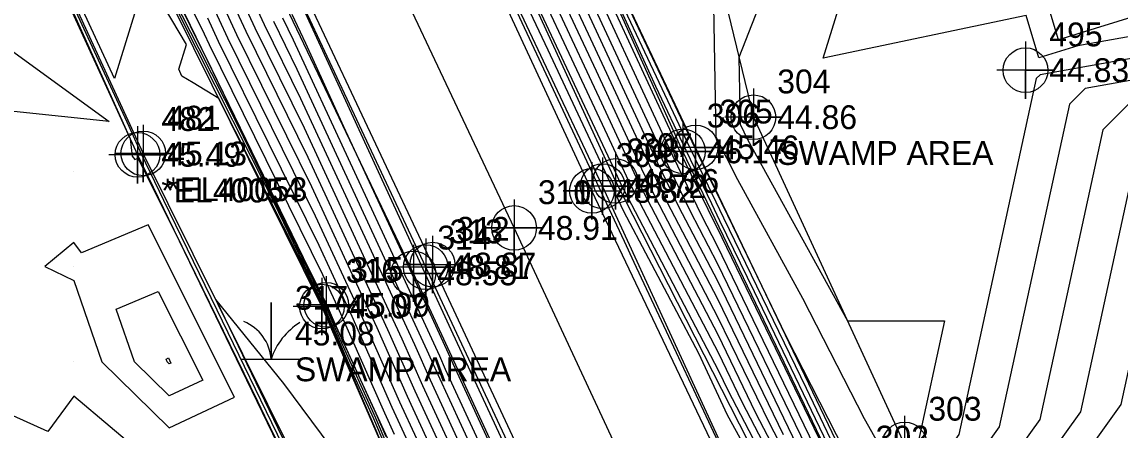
# Model space of a CAD drawing. Extents: x 2090860 to 2091277, y 159470 to 160080.
# Drawn here: x 2090954.6 to 2091069.7, y 159862.9 to 159905.6 of the extents above; entities that cross this region are included whole.
import ezdxf

# ---------------------------------------------------------------- set-up
doc = ezdxf.new("R2010")
doc.units = 0
for name, color, linetype in [('DTM Contours Major', 7, 'Continuous'), ('DTM Contours Minor', 7, 'Continuous'), ('Exist DTM Breakline', 7, 'Continuous'), ('Exist DTM Breakline Cogo Comment', 7, 'Continuous'), ('Exist DTM Breakline Cogo Elevation', 7, 'Continuous'), ('Exist DTM Breakline Cogo Number', 7, 'Continuous'), ('Exist DTM Breakline Cogo Point CELL', 7, 'Continuous'), ('Exist DTM Breakline Underwater', 7, 'Continuous'), ('Exist DTM Crownline', 7, 'Continuous'), ('Exist DTM Crownline Cogo Elevation', 7, 'Continuous'), ('Exist DTM Crownline Cogo Number', 7, 'Continuous'), ('Exist DTM Crownline Cogo Point CELL', 7, 'Continuous'), ('Exist DTM QL2 LIDAR Elevation Point', 7, 'Continuous'), ('Exist DTM Regular Point CELL', 7, 'Continuous'), ('Exist DTM Regular Point Cogo Elevation', 7, 'Continuous'), ('Exist DTM Regular Point Cogo Number', 7, 'Continuous'), ('Exist Hydro Swamp or Marsh', 7, 'Continuous'), ('Exist Hydro Swamp or Marsh Cogo Comment', 7, 'Continuous'), ('Exist Hydro Swamp or Marsh Cogo Elevation', 7, 'Continuous'), ('Exist Hydro Swamp or Marsh Cogo Number', 7, 'Continuous'), ('Exist Roads EOP', 7, 'Continuous'), ('Exist Roads EOP Cogo Elevation', 7, 'Continuous'), ('Exist Roads EOP Cogo Number', 7, 'Continuous'), ('Exist Roads EOP Cogo Point CELL', 7, 'Continuous'), ('Exist Roads EOT', 7, 'Continuous'), ('Exist Roads EOT Cogo Elevation', 7, 'Continuous'), ('Exist Roads EOT Cogo Number', 7, 'Continuous'), ('Exist Roads EOT Cogo Point CELL', 7, 'Continuous')]:
    doc.layers.add(name, color=color, linetype=linetype)

msp = doc.modelspace()

# ---------------------------------------------------------------- linework, layer by layer
at = {"layer": 'DTM Contours Major'}
for points in [[(2091039.97, 159928.18), (2091029.72, 159901.93), (2091029.84, 159894.93), (2091030.64, 159893.33), (2091041.09, 159874.33), (2091046.74, 159874.32), (2091051.28, 159874.32), (2091048.51, 159861.61), (2091048.02, 159860.92), (2091052.61, 159846.51), (2091052.56, 159846.24), (2091064.7, 159822.8), (2091063.82, 159819.49), (2091056.74, 159812.83), (2091055.87, 159811.45), (2091055.8, 159811.41), (2091054.88, 159810.97), (2091050.57, 159808.88), (2091033.91, 159797.01), (2091031.48, 159794.62), (2091026.53, 159778.36)], [(2091083.65, 159906.42), (2091065.23, 159903.13), (2091061.17, 159901.88), (2091059.83, 159906.32), (2091038.54, 159901.84), (2091046.68, 159928.13)], [(2090955.45, 159918.84), (2090963.16, 159912.58), (2090966.53, 159906.94), (2090964.27, 159899.73), (2090955.45, 159918.84)], [(2091040.77, 159857.8), (2091031.34, 159877.37), (2091027.73, 159884.81), (2091026.88, 159886.57), (2091024.18, 159892.18), (2091021.02, 159898.88), (2091011.64, 159919.46)], [(2091041.05, 159844.71), (2091030.07, 159865.8), (2091027.57, 159870.96), (2091018.54, 159888.26), (2091017.95, 159889.49), (2091015.95, 159893.79), (2091005.23, 159916.67)], [(2090967.46, 159914.98), (2090973.01, 159903.6), (2090973.34, 159902.96), (2090973.84, 159901.97), (2090984.06, 159880.95), (2090986.46, 159876.09), (2090986.5, 159876), (2090986.52, 159875.97), (2090987.34, 159874.09), (2090991.85, 159864.2), (2090992.7, 159862.2)], [(2090974.73, 159909.42), (2090977.08, 159904.33), (2090984.93, 159888.39), (2090990.07, 159877.29), (2090991.77, 159873.61), (2090994.95, 159866.4), (2090999.75, 159856)], [(2091035.84, 159861.21), (2091027.5, 159878.46), (2091023.43, 159886.26), (2091021.18, 159890.91), (2091013.64, 159907.17)], [(2090980.93, 159905.73), (2090983.4, 159900.7), (2090993.64, 159878.58), (2090997.02, 159871.25), (2090998.15, 159868.69), (2091007.95, 159847.44)], [(2091091.58, 159898.64), (2091075.46, 159895.75), (2091071.36, 159891.65), (2091065.51, 159864.77), (2091059.16, 159855.9), (2091062.53, 159845.34), (2091062.38, 159844.53), (2091071.24, 159827.42), (2091068.47, 159817.05), (2091062.55, 159811.48), (2091060.26, 159801.48), (2091046.88, 159791.94), (2091037.59, 159782.8), (2091031.99, 159764.38), (2091026.69, 159760.21), (2091021.29, 159752.69), (2091014.87, 159747.47), (2091001.67, 159730.12), (2090998.42, 159727.26), (2090990.82, 159719.67), (2090976.25, 159706.99)], [(2090968.87, 159877.39), (2090973.52, 159868.09), (2090970, 159866.45), (2090966.37, 159870), (2090964.45, 159875.55), (2090968.87, 159877.39)], [(2091016.71, 159800.2), (2091008.38, 159811.91), (2091004.99, 159818.47), (2091002.26, 159829.04), (2091000.51, 159832.57), (2090997.86, 159833.56), (2090989.84, 159850.89), (2090987.9, 159859.84), (2090982.04, 159867.75), (2090974.9, 159876.54), (2090983.75, 159858.2), (2090986.81, 159851.93), (2090996.12, 159832.68), (2090997.83, 159829.17), (2090999.89, 159824.93), (2091004.42, 159815.54), (2091007.3, 159809.55), (2091015.2, 159792.84), (2091016.71, 159800.2)]]:
    msp.add_lwpolyline(points, dxfattribs=at)
at = {"layer": 'DTM Contours Minor'}
for points in [[(2090953.06, 159921.96), (2090965.05, 159895.34), (2090965.36, 159894.66), (2090965.92, 159893.4), (2090966.12, 159891.57), (2090966.4, 159891.21), (2090966.74, 159891.35), (2090970.6, 159883.65), (2090979.25, 159865.89), (2090980, 159864.34), (2090992.07, 159839.55), (2090993.27, 159837.07), (2090997.16, 159829.09), (2091001.85, 159819.43), (2091003.89, 159815.2), (2091014.81, 159792.51), (2091016.87, 159788.26), (2091017.43, 159786.84), (2091024.63, 159765.9)], [(2091041.7, 159858.95), (2091034.7, 159872.63), (2091028.55, 159885.34), (2091025.32, 159892.03), (2091025.1, 159892.47), (2091012.73, 159918.74)], [(2091040.87, 159848.3), (2091032.95, 159863.5), (2091027.53, 159874.71), (2091020.98, 159887.26), (2091019.56, 159890.2), (2091014.79, 159900.48), (2091006.87, 159917.39)], [(2091034.39, 159862.36), (2091027.52, 159876.59), (2091022.21, 159886.76), (2091020.37, 159890.55), (2091014.22, 159903.83), (2091007.7, 159917.75)], [(2091040.16, 159857.78), (2091027.45, 159884.09), (2091027.09, 159884.77), (2091023.61, 159891.97), (2091011.91, 159917.21)], [(2091041.13, 159842.92), (2091028.63, 159866.94), (2091027.59, 159869.09), (2091017.32, 159888.76), (2091017.14, 159889.13), (2091016.53, 159890.45), (2091004.41, 159916.31)], [(2091040.96, 159846.5), (2091031.51, 159864.65), (2091027.55, 159872.84), (2091019.76, 159887.76), (2091018.75, 159889.84), (2091015.37, 159897.14), (2091006.05, 159917.03)], [(2090968.28, 159915.35), (2090973.67, 159904.41), (2090974.2, 159903.27), (2090986.08, 159879.16), (2090987.4, 159876.32), (2090987.83, 159875.38), (2090992.56, 159864.68), (2090993.6, 159862.42)], [(2091039.08, 159845.24), (2091028.52, 159864.43), (2091025.51, 159870.89), (2091017.65, 159885.76), (2091016.26, 159888.76), (2091009.72, 159902.68), (2091003.49, 159915.92)], [(2091018.49, 159801.2), (2091016.34, 159804.22), (2091005.91, 159824.4), (2091004.75, 159828.91), (2091001.89, 159834.69), (2091000.66, 159835.15), (2090996.96, 159843.16), (2090993.72, 159858.07), (2090991.18, 159864.04), (2090990.78, 159864.92), (2090986.1, 159875.84), (2090983.69, 159880.8), (2090975.23, 159897.62), (2090972.54, 159899.28), (2090971.35, 159899.98), (2090971.03, 159900.71), (2090971.84, 159903.3), (2090965.56, 159913.82)], [(2090975.78, 159914.43), (2090979.97, 159905.38), (2090983.78, 159897.63), (2090992.75, 159878.26), (2090995.71, 159871.84), (2090997.35, 159868.12), (2091005.9, 159849.58)], [(2091038.72, 159858.92), (2091027.46, 159882.21), (2091025.87, 159885.26), (2091022.8, 159891.62), (2091012.48, 159913.86)], [(2091073.27, 159906.87), (2091063.23, 159903.77), (2091059.94, 159914.75)], [(2090957.42, 159912.81), (2090965.77, 159894.72), (2090966.22, 159893.71), (2090967.09, 159891.81), (2090969.43, 159886.95), (2090975.02, 159875.46), (2090981.88, 159861.27), (2090989.44, 159845.74), (2090994.7, 159834.88), (2090997.49, 159829.13), (2091000.87, 159822.18), (2091004.15, 159815.37), (2091013, 159797), (2091016.23, 159790.16), (2091018.49, 159801.2)], [(2090975.43, 159912.76), (2090979, 159905.03), (2090984.17, 159894.55), (2090991.86, 159877.93), (2090994.39, 159872.43), (2090996.55, 159867.54), (2091003.85, 159851.72)], [(2091026.97, 159913.29), (2091027.29, 159893.6), (2091029.56, 159889.12), (2091036.39, 159876.69), (2091042.85, 159864.08), (2091045.03, 159860.22), (2091047.26, 159855.83), (2091050.13, 159846.8), (2091050.11, 159846.66), (2091063.07, 159821.65), (2091062.65, 159820.1), (2091059.35, 159816.99), (2091056, 159811.66), (2091055.72, 159811.5), (2091052.18, 159809.82), (2091035.58, 159801.78), (2091030.67, 159798.28), (2091029.95, 159797.57), (2091028.49, 159792.78), (2091019.08, 159782.23), (2091024.7, 159765.88)], [(2090940, 159891.29), (2090936.92, 159900), (2090935.7, 159904.3), (2090938.59, 159910), (2090940, 159911.7), (2090940.62, 159910.62), (2090943.07, 159910), (2090950, 159905.16), (2090963.73, 159895.22), (2090953.73, 159896.27), (2090950, 159897.83), (2090943.46, 159896.54), (2090940, 159891.29)], [(2090968, 159912.5), (2090972.9, 159902.77), (2090980.41, 159887.86), (2090986.23, 159875.89), (2090989.33, 159868.65), (2090991.41, 159864.09), (2091002.4, 159838.19)], [(2090975.08, 159911.09), (2090978.04, 159904.68), (2090984.55, 159891.47), (2090990.96, 159877.61), (2090993.08, 159873.02), (2090995.75, 159866.97), (2091001.8, 159853.86)], [(2091037.28, 159860.07), (2091027.48, 159880.34), (2091024.65, 159885.76), (2091021.99, 159891.26), (2091013.06, 159910.52)], [(2090970.51, 159908.05), (2090973.12, 159902.87), (2090977.12, 159894.92), (2090986.35, 159875.94), (2090987.88, 159872.38), (2090991.63, 159864.14), (2090997.55, 159850.2)], [(2091029.68, 159857.09), (2091018.76, 159880.42), (2091017.73, 159882.64), (2091015.09, 159888.28), (2091005.49, 159908.79)], [(2091041.19, 159858.08), (2091036.79, 159867.21), (2091028.14, 159885.08), (2091026.1, 159889.3), (2091024.64, 159892.33), (2091016.88, 159908.81)], [(2090974.38, 159907.75), (2090976.12, 159903.97), (2090985.32, 159885.32), (2090989.18, 159876.97), (2090990.46, 159874.2), (2090994.15, 159865.83), (2090997.7, 159858.14)], [(2090984.06, 159907.05), (2090994.33, 159884.72), (2090996.59, 159879.78), (2090999.75, 159872.94), (2091000.9, 159870.46), (2091009.47, 159851.94)], [(2090974.02, 159906.08), (2090975.16, 159903.62), (2090985.7, 159882.24), (2090988.29, 159876.64), (2090989.14, 159874.79), (2090993.36, 159865.25), (2090995.65, 159860.28)], [(2090981.89, 159906.08), (2090983.02, 159903.78), (2090994.53, 159878.9), (2090998.33, 159870.66), (2090998.95, 159869.26), (2091010, 159845.3)], [(2090982.88, 159906.46), (2090984.29, 159903.41), (2090988.28, 159894.67), (2090995.43, 159879.23), (2090999.64, 159870.08), (2090999.75, 159869.83), (2091012.05, 159843.16)], [(2091085.63, 159904.48), (2091061.28, 159900.12), (2091060.88, 159899.72), (2091052.76, 159862.4), (2091050.81, 159859.67), (2091055.09, 159846.22), (2091055.02, 159845.81), (2091066.34, 159823.96), (2091064.98, 159818.88), (2091057.02, 159811.39), (2091056.62, 159809.61), (2091037.15, 159795.75), (2091033, 159791.66), (2091025.13, 159765.78), (2091024.91, 159765.61), (2091017.66, 159755.48), (2091016.24, 159754.33), (2090999.2, 159731.95), (2090995, 159728.26), (2090991.7, 159724.95), (2090972.2, 159707.99)], [(2091087.61, 159902.53), (2091066.01, 159898.66), (2091064.37, 159897.03), (2091057.01, 159863.19), (2091053.59, 159858.41), (2091057.57, 159845.93), (2091057.47, 159845.38), (2091067.97, 159825.11), (2091066.14, 159818.27), (2091058.87, 159811.42), (2091057.83, 159806.9), (2091040.39, 159794.48), (2091034.53, 159788.71), (2091027.42, 159765.32), (2091025.5, 159763.81), (2091018.87, 159754.55), (2091015.78, 159752.04), (2091000.02, 159731.34), (2090996.14, 159727.93), (2090991.4, 159723.19), (2090973.55, 159707.65)], [(2091089.6, 159900.58), (2091070.73, 159897.21), (2091067.87, 159894.34), (2091061.26, 159863.98), (2091056.38, 159857.16), (2091060.05, 159845.64), (2091059.93, 159844.95), (2091069.61, 159826.27), (2091067.31, 159817.66), (2091060.71, 159811.45), (2091059.04, 159804.19), (2091043.63, 159793.21), (2091036.06, 159785.76), (2091029.7, 159764.85), (2091026.1, 159762.01), (2091020.08, 159753.62), (2091015.33, 159749.76), (2091000.85, 159730.73), (2090997.28, 159727.59), (2090991.11, 159721.43), (2090974.9, 159707.32)], [(2091093.57, 159896.69), (2091080.19, 159894.3), (2091074.85, 159888.96), (2091069.76, 159865.56), (2091061.95, 159854.65), (2091065.01, 159845.05), (2091064.84, 159844.1), (2091072.88, 159828.58), (2091069.63, 159816.44), (2091064.4, 159811.51), (2091061.47, 159798.77), (2091050.12, 159790.68), (2091039.11, 159779.85), (2091034.27, 159763.92), (2091027.28, 159758.42), (2091022.51, 159751.76), (2091014.42, 159745.18), (2091002.49, 159729.52), (2090999.55, 159726.93), (2090990.53, 159717.91), (2090977.6, 159706.66)], [(2090960.83, 159881.45), (2090960, 159882.51), (2090956.99, 159880), (2090960, 159878.53), (2090962.95, 159870), (2090970, 159863.1), (2090976.85, 159866.3), (2090967.81, 159884.37), (2090960.83, 159881.45)], [(2090969.94, 159870.42), (2090970.2, 159869.89), (2090970, 159869.8), (2090969.8, 159870), (2090969.69, 159870.31), (2090969.94, 159870.42)], [(2090950, 159825.48), (2090955.6, 159824.4), (2090960, 159827.48), (2090963.77, 159826.23), (2090965.4, 159830), (2090960, 159834.42), (2090956.89, 159840), (2090953.21, 159846.79), (2090960, 159844.15), (2090963.48, 159846.52), (2090962.38, 159850), (2090961.73, 159858.27), (2090967.63, 159860), (2090960, 159866.42), (2090957.3, 159862.7), (2090950, 159866.01)]]:
    msp.add_lwpolyline(points, dxfattribs=at)
at = {"layer": 'Exist DTM Breakline'}
for p, q in [((2090966.69, 159891.72), (2090997.04, 159829.07)), ((2090998.35, 159829.24), (2090967.3, 159891.86))]:
    msp.add_line(p, q, dxfattribs=at)
for points in [[(2091060.14, 159819.74), (2091040.42, 159857.57), (2091023.86, 159892.08), (2091004.98, 159933.93), (2090988.92, 159970.75), (2090947.97, 160061.8)], [(2091061.63, 159820.63), (2091041.56, 159858.32), (2091025.18, 159892.5), (2091005.43, 159934.28), (2090989.69, 159971.2), (2090948.62, 160062.01)], [(2091054.85, 159814.3), (2091016.78, 159888.98), (2090997.77, 159930.43), (2090980.35, 159966.51), (2090937.84, 160056.58)], [(2091012.48, 159842.71), (2090995.61, 159879.29), (2090976.73, 159918.9), (2090959.8, 159955.65), (2090940.36, 159997.15), (2090917.63, 160046.58)], [(2091019.11, 159801.55), (2091003.08, 159836.51), (2090986.02, 159875.81), (2090966.87, 159914.51), (2090949.07, 159951.29), (2090930.11, 159992.15), (2090906.43, 160041.55)], [(2091019.81, 159801.91), (2091004.42, 159836.95), (2090986.48, 159875.99), (2090967.52, 159915.03), (2090950.04, 159951.45), (2090930.7, 159992.43), (2090908.05, 160042.23)], [(2090898.02, 160040.01), (2090922.13, 159989.7), (2090940.87, 159949.25), (2090967.3, 159891.86)], [(2090895.73, 160038.67), (2090921.91, 159989.02), (2090940.35, 159949.21), (2090966.69, 159891.72)]]:
    msp.add_lwpolyline(points, dxfattribs=at)
at = {"layer": 'Exist DTM Breakline Cogo Point CELL'}
for points in [[(2091031.24, 159898.66), (2091031.24, 159892.66), (2091031.24, 159895.66), (2091034.24, 159895.66), (2091028.24, 159895.66)], [(2091025.18, 159895.5), (2091025.18, 159889.5), (2091025.18, 159892.5), (2091028.18, 159892.5), (2091022.18, 159892.5)], [(2090966.69, 159894.72), (2090966.69, 159888.72), (2090966.69, 159891.72), (2090969.69, 159891.72), (2090963.69, 159891.72)], [(2090967.3, 159894.86), (2090967.3, 159888.86), (2090967.3, 159891.86), (2090970.3, 159891.86), (2090964.3, 159891.86)], [(2091023.86, 159895.08), (2091023.86, 159889.08), (2091023.86, 159892.08), (2091026.86, 159892.08), (2091020.86, 159892.08)], [(2091016.78, 159891.98), (2091016.78, 159885.98), (2091016.78, 159888.98), (2091019.78, 159888.98), (2091013.78, 159888.98)], [(2090995.61, 159882.29), (2090995.61, 159876.29), (2090995.61, 159879.29), (2090998.61, 159879.29), (2090992.61, 159879.29)], [(2090986.02, 159878.81), (2090986.02, 159872.81), (2090986.02, 159875.81), (2090989.02, 159875.81), (2090983.02, 159875.81)], [(2090986.48, 159878.99), (2090986.48, 159872.99), (2090986.48, 159875.99), (2090989.48, 159875.99), (2090983.48, 159875.99)], [(2091047.08, 159864.35), (2091047.08, 159858.35), (2091047.08, 159861.35), (2091050.08, 159861.35), (2091044.08, 159861.35)]]:
    msp.add_lwpolyline(points, dxfattribs=at)
for centre in [(2091031.24, 159895.66), (2090967.3, 159891.86), (2091023.86, 159892.08), (2091025.18, 159892.5), (2090966.69, 159891.72), (2091016.78, 159888.98), (2090995.61, 159879.29), (2090986.02, 159875.81), (2090986.48, 159875.99), (2091047.08, 159861.35)]:
    msp.add_circle(centre, 2.34, dxfattribs=at)
at = {"layer": 'Exist DTM Breakline Underwater'}
msp.add_lwpolyline([(2091025.27, 159920.29), (2091031.24, 159895.66), (2091047.08, 159861.35)], dxfattribs=at)
at = {"layer": 'Exist DTM Crownline'}
msp.add_lwpolyline([(2091041.9, 159807.58), (2091022.74, 159848.48), (2091006.16, 159884.05), (2090987.2, 159924.29), (2090970.35, 159960.93), (2090951.23, 160001.94), (2090928.33, 160051.75)], dxfattribs=at)
at = {"layer": 'Exist DTM Crownline Cogo Point CELL'}
msp.add_lwpolyline([(2091006.16, 159887.05), (2091006.16, 159881.05), (2091006.16, 159884.05), (2091009.16, 159884.05), (2091003.16, 159884.05)], dxfattribs=at)
msp.add_circle((2091006.16, 159884.05), 2.34, dxfattribs=at)
at = {"layer": 'Exist DTM QL2 LIDAR Elevation Point'}
for p, q in [((2090960, 159890), (2090960, 159890)), ((2090960, 159880), (2090960, 159880)), ((2090960, 159870), (2090960, 159870)), ((2090970, 159870), (2090970, 159870))]:
    msp.add_line(p, q, dxfattribs=at)
at = {"layer": 'Exist DTM Regular Point CELL'}
msp.add_lwpolyline([(2091059.76, 159903.59), (2091059.76, 159897.59), (2091059.76, 159900.59), (2091062.76, 159900.59), (2091056.76, 159900.59)], dxfattribs=at)
msp.add_circle((2091059.76, 159900.59), 2.34, dxfattribs=at)
at = {"layer": 'Exist Hydro Swamp or Marsh'}
msp.add_line((2090980.69, 159872.98), (2090980.69, 159872.98), dxfattribs=at)
msp.add_lwpolyline([(2090977.47, 159870.31), (2090980.69, 159870.31), (2090980.69, 159876.22), (2090980.69, 159870.31), (2090983.92, 159870.31)], dxfattribs=at)
for centre, radius, start, end in [((2090976.09, 159869.97), 4.61, 4.1403, 67.535), ((2090987.54, 159868.03), 7.21, 122.1274, 161.6222)]:
    msp.add_arc(centre, radius, start, end, dxfattribs=at)
at = {"layer": 'Exist Roads EOP'}
for points in [[(2091050.89, 159811.95), (2091031.57, 159853.36), (2091015.44, 159888.43), (2090996.02, 159929.56), (2090979.12, 159965.86), (2090960.14, 160006.79), (2090936.88, 160056.11)], [(2091032.87, 159803.47), (2091013.96, 159843.47), (2090996.9, 159879.94), (2090978.32, 159919.67), (2090961.24, 159956.49), (2090941.84, 159997.89), (2090918.79, 160047.28)]]:
    msp.add_lwpolyline(points, dxfattribs=at)
at = {"layer": 'Exist Roads EOP Cogo Point CELL'}
for points in [[(2091015.44, 159891.43), (2091015.44, 159885.43), (2091015.44, 159888.43), (2091018.44, 159888.43), (2091012.44, 159888.43)], [(2090996.9, 159882.94), (2090996.9, 159876.94), (2090996.9, 159879.94), (2090999.9, 159879.94), (2090993.9, 159879.94)]]:
    msp.add_lwpolyline(points, dxfattribs=at)
for centre in [(2091015.44, 159888.43), (2090996.9, 159879.94)]:
    msp.add_circle(centre, 2.34, dxfattribs=at)
at = {"layer": 'Exist Roads EOT'}
for points in [[(2091050.36, 159811.62), (2091031, 159852.89), (2091014.32, 159887.94), (2090995.23, 159929.1), (2090978.27, 159965.51), (2090959.41, 160006.45), (2090936.3, 160055.79)], [(2091033.43, 159803.71), (2091014.62, 159843.76), (2090997.61, 159880.21), (2090978.9, 159919.95), (2090961.79, 159956.63), (2090942.52, 159998.3), (2090919.61, 160047.64)]]:
    msp.add_lwpolyline(points, dxfattribs=at)
at = {"layer": 'Exist Roads EOT Cogo Point CELL'}
for points in [[(2091014.32, 159890.94), (2091014.32, 159884.94), (2091014.32, 159887.94), (2091011.32, 159887.94), (2091017.32, 159887.94)], [(2091006.16, 159887.05), (2091006.16, 159881.05), (2091006.16, 159884.05), (2091003.16, 159884.05), (2091009.16, 159884.05)], [(2090997.61, 159883.21), (2090997.61, 159877.21), (2090997.61, 159880.21), (2090994.61, 159880.21), (2091000.61, 159880.21)]]:
    msp.add_lwpolyline(points, dxfattribs=at)
for centre in [(2091014.32, 159887.94), (2091006.16, 159884.05), (2090997.61, 159880.21)]:
    msp.add_circle(centre, 2.34, dxfattribs=at)

# ---------------------------------------------------------------- texts
at = {"layer": 'Exist DTM Breakline Cogo Comment'}
for s, p in [('SWAMP AREA', (2091033.74, 159890.66)), ('*EL40054', (2090969.19, 159886.72)), ('*EL40053', (2090969.8, 159886.86))]:
    msp.add_text(s, height=2.5, dxfattribs=at).set_placement(p)
at = {"layer": 'Exist DTM Breakline Cogo Elevation'}
for s, p in [('44.86', (2091033.74, 159894.41)), ('45.13', (2090969.8, 159890.61)), ('46.17', (2091026.36, 159890.83)), ('45.46', (2091027.68, 159891.25)), ('45.49', (2090969.19, 159890.47)), ('48.36', (2091019.28, 159887.73)), ('48.55', (2090998.11, 159878.04)), ('45.07', (2090988.52, 159874.56)), ('45.99', (2090988.98, 159874.74))]:
    msp.add_text(s, height=2.5, dxfattribs=at).set_placement(p)
at = {"layer": 'Exist DTM Breakline Cogo Number'}
for s, p in [('304', (2091033.74, 159898.16)), ('482', (2090969.19, 159894.22)), ('481', (2090969.8, 159894.36)), ('306', (2091026.36, 159894.58)), ('305', (2091027.68, 159895)), ('307', (2091019.28, 159891.48)), ('314', (2090998.11, 159881.79)), ('316', (2090988.52, 159878.31)), ('315', (2090988.98, 159878.49)), ('303', (2091049.58, 159863.85)), ('302', (2091044.06, 159860.82))]:
    msp.add_text(s, height=2.5, dxfattribs=at).set_placement(p)
at = {"layer": 'Exist DTM Crownline Cogo Elevation'}
msp.add_text('48.91', height=2.5, dxfattribs=at).set_placement((2091008.66, 159882.8))
at = {"layer": 'Exist DTM Crownline Cogo Number'}
msp.add_text('311', height=2.5, dxfattribs=at).set_placement((2091008.66, 159886.55))
at = {"layer": 'Exist DTM Regular Point Cogo Elevation'}
msp.add_text('44.83', height=2.5, dxfattribs=at).set_placement((2091062.26, 159899.34))
at = {"layer": 'Exist DTM Regular Point Cogo Number'}
msp.add_text('495', height=2.5, dxfattribs=at).set_placement((2091062.26, 159903.09))
at = {"layer": 'Exist Hydro Swamp or Marsh Cogo Comment'}
msp.add_text('SWAMP AREA', height=2.5, dxfattribs=at).set_placement((2090983.19, 159867.98))
at = {"layer": 'Exist Hydro Swamp or Marsh Cogo Elevation'}
msp.add_text('45.08', height=2.5, dxfattribs=at).set_placement((2090983.19, 159871.73))
at = {"layer": 'Exist Hydro Swamp or Marsh Cogo Number'}
msp.add_text('317', height=2.5, dxfattribs=at).set_placement((2090983.19, 159875.48))
at = {"layer": 'Exist Roads EOP Cogo Elevation'}
for s, p in [('48.72', (2091017.94, 159887.18)), ('48.81', (2090999.4, 159878.69))]:
    msp.add_text(s, height=2.5, dxfattribs=at).set_placement(p)
at = {"layer": 'Exist Roads EOP Cogo Number'}
for s, p in [('308', (2091017.94, 159890.93)), ('313', (2090999.4, 159882.44))]:
    msp.add_text(s, height=2.5, dxfattribs=at).set_placement(p)
at = {"layer": 'Exist Roads EOT Cogo Elevation'}
for s, p in [('48.82', (2091016.82, 159886.69)), ('48.91', (2091008.66, 159882.8)), ('48.87', (2091000.11, 159878.96))]:
    msp.add_text(s, height=2.5, dxfattribs=at).set_placement(p)
at = {"layer": 'Exist Roads EOT Cogo Number'}
for s, p in [('309', (2091016.82, 159890.44)), ('310', (2091008.66, 159886.55)), ('312', (2091000.11, 159882.71))]:
    msp.add_text(s, height=2.5, dxfattribs=at).set_placement(p)

doc.saveas('drawing.dxf')
